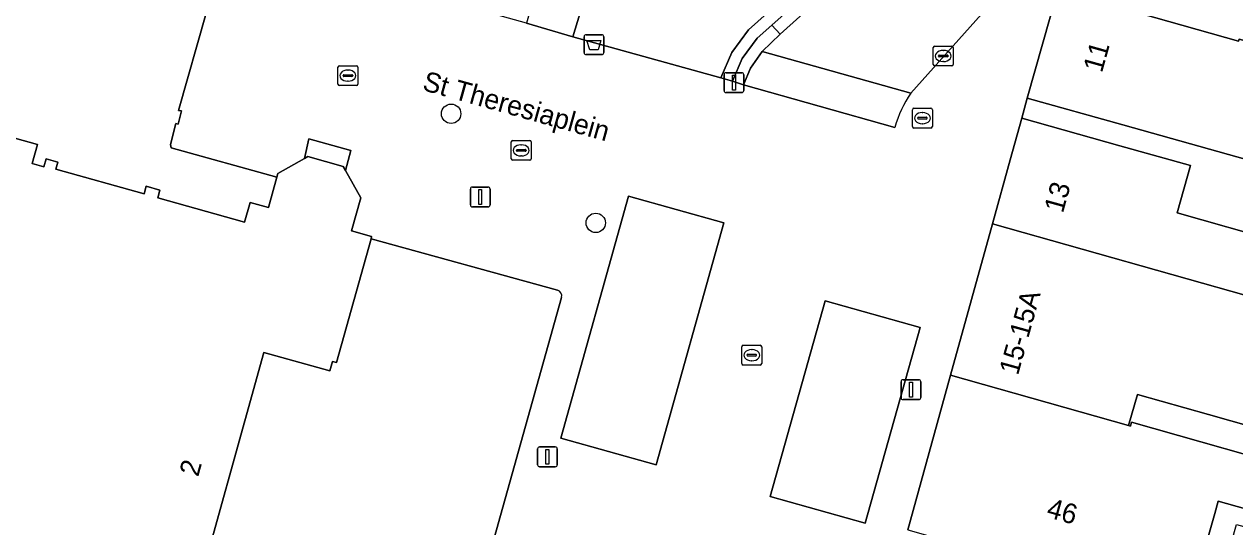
# Model space of a CAD drawing. Extents: x 158086 to 159499, y 382904 to 383981.
# Drawn here: x 158668.8 to 158729.8, y 383258 to 383283.3 of the extents above; entities that cross this region are included whole.
import ezdxf

# ---------------------------------------------------------------- set-up
doc = ezdxf.new("R2010")
doc.units = 0
for name, color, linetype in [('IMGEO_Afvalbak', 7, 'Continuous'), ('IMGEO_Boom', 7, 'Continuous'), ('IMGEO_Erf', 7, 'Continuous'), ('IMGEO_Groenvoorziening', 7, 'Continuous'), ('IMGEO_Haag', 7, 'Continuous'), ('IMGEO_Kolk', 7, 'Continuous'), ('IMGEO_Lichtmast', 7, 'Continuous'), ('IMGEO_Openbare_ruimte_label', 7, 'Continuous'), ('IMGEO_Pand', 7, 'Continuous'), ('IMGEO_Pand_nummerreeks', 7, 'Continuous'), ('IMGEO_Parkeervlak_open', 7, 'Continuous'), ('IMGEO_Rijbaan_lokaal_open', 7, 'Continuous'), ('IMGEO_Rioolput', 7, 'Continuous'), ('IMGEO_Voetpad_open', 7, 'Continuous')]:
    doc.layers.add(name, color=color, linetype=linetype)

msp = doc.modelspace()

# ---------------------------------------------------------------- linework, layer by layer
at = {"layer": 'IMGEO_Afvalbak'}
for p, q in [((158697.033, 383281.862), (158697.033, 383282.662)), ((158697.033, 383282.662), (158697.033, 383281.862)), ((158697.133, 383282.762), (158697.923, 383282.762)), ((158697.923, 383282.762), (158697.133, 383282.762)), ((158698.023, 383282.662), (158698.023, 383281.862)), ((158698.023, 383281.862), (158698.023, 383282.662)), ((158697.923, 383281.762), (158697.133, 383281.762)), ((158697.133, 383281.762), (158697.923, 383281.762))]:
    msp.add_line(p, q, dxfattribs=at)
msp.add_lwpolyline([(158697.176, 383282.476), (158697.88, 383282.476), (158697.731, 383282.006), (158697.325, 383282.006), (158697.176, 383282.476)], dxfattribs=at)
for centre, start, end in [((158697.133, 383282.662), 90, 180), ((158697.133, 383282.662), 90, 180), ((158697.923, 383282.662), 0, 90), ((158697.923, 383282.662), 360, 90), ((158697.133, 383281.862), 180, 270), ((158697.133, 383281.862), 180, 270), ((158697.923, 383281.862), 270, 0), ((158697.923, 383281.862), 270, 0)]:
    msp.add_arc(centre, 0.1, start, end, dxfattribs=at)
at = {"layer": 'IMGEO_Boom'}
for centre in [(158690.335, 383278.783), (158697.618, 383273.285)]:
    msp.add_circle(centre, 0.489, dxfattribs=at)
at = {"layer": 'IMGEO_Erf'}
for points in [[(158666.186, 383278.161), (158669.502, 383277.236), (158669.235, 383276.276), (158669.827, 383276.111), (158669.94, 383276.516), (158670.533, 383276.35), (158670.432, 383275.986), (158674.874, 383274.747), (158674.981, 383275.131), (158675.671, 383274.939), (158675.56, 383274.542), (158679.931, 383273.322), (158680.208, 383274.315), (158681.134, 383274.057), (158681.562, 383275.592), (158676.233, 383277.07), (158676.208, 383277.235), (158676.469, 383278.293), (158676.582, 383278.26), (158676.752, 383278.933), (158676.609, 383278.949), (158678, 383283.841), (158673.649, 383285.053), (158667.187, 383286.853)], [(158733.304, 383275.655), (158724.166, 383278.217), (158719.351, 383279.567), (158719.072, 383278.559), (158724.007, 383277.16), (158727.562, 383276.172), (158726.893, 383273.794), (158731.984, 383272.351)], [(158695.684, 383269.895), (158686.301, 383272.487), (158684.562, 383266.252), (158684.363, 383266.307), (158684.231, 383265.832), (158680.902, 383266.761), (158677.157, 383253.287)], [(158683.323, 383224.573), (158695.899, 383269.524)]]:
    msp.add_lwpolyline(points, dxfattribs=at)
msp.add_lwpolyline([(158731.056, 383257.778), (158731.292, 383258.611), (158728.963, 383259.271), (158728.786, 383258.646), (158727.422, 383253.835), (158731.469, 383252.723), (158731.473, 383252.737), (158731.567, 383253.068), (158731.35, 383253.13), (158730.129, 383253.476), (158728.69, 383253.884), (158729.885, 383258.097)], close=True, dxfattribs=at)
msp.add_arc((158695.601, 383269.599), 0.307, 345.85771, 74.32814, dxfattribs=at)
at = {"layer": 'IMGEO_Groenvoorziening'}
for points in [[(158715.651, 383319.137), (158708.346, 383292.883), (158713.145, 383291.584), (158712.877, 383290.631), (158712.4, 383289.615), (158711.72, 383288.771), (158708.905, 383286.24), (158705.305, 383283.005), (158704.465, 383281.869), (158703.916, 383280.587), (158704.499, 383280.425), (158704.989, 383281.568), (158705.749, 383282.597), (158706.491, 383283.248), (158709.467, 383285.933)], [(158701.326, 383284.735), (158697.345, 383285.602), (158696.463, 383282.664), (158703.916, 383280.587), (158704.465, 383281.869), (158705.305, 383283.005), (158708.905, 383286.24), (158708.372, 383286.529), (158707.006, 383286.118)]]:
    msp.add_lwpolyline(points, dxfattribs=at)
at = {"layer": 'IMGEO_Haag'}
msp.add_lwpolyline([(158715.651, 383319.137), (158708.346, 383292.883), (158713.145, 383291.584), (158712.877, 383290.631), (158712.4, 383289.615), (158711.72, 383288.771), (158708.905, 383286.24), (158705.305, 383283.005), (158704.465, 383281.869), (158703.916, 383280.587), (158704.499, 383280.425), (158704.989, 383281.568), (158705.749, 383282.597), (158706.491, 383283.248), (158709.467, 383285.933)], dxfattribs=at)
at = {"layer": 'IMGEO_Kolk'}
for p, q in [((158714.617, 383281.266), (158714.617, 383282.118)), ((158714.692, 383282.192), (158715.544, 383282.192)), ((158714.876, 383281.686), (158714.876, 383281.698)), ((158714.919, 383281.735), (158715.317, 383281.735)), ((158715.105, 383281.972), (158715.13, 383281.972)), ((158715.36, 383281.698), (158715.36, 383281.686)), ((158715.618, 383282.118), (158715.618, 383281.266)), ((158684.636, 383280.277), (158684.636, 383281.129)), ((158684.711, 383281.203), (158685.563, 383281.203)), ((158685.637, 383281.129), (158685.637, 383280.277)), ((158715.544, 383281.192), (158714.692, 383281.192)), ((158715.314, 383281.649), (158714.916, 383281.649)), ((158715.128, 383281.412), (158715.103, 383281.412)), ((158684.895, 383280.697), (158684.895, 383280.709)), ((158685.333, 383280.66), (158684.935, 383280.66)), ((158684.938, 383280.746), (158685.336, 383280.746)), ((158685.124, 383280.983), (158685.149, 383280.983)), ((158685.379, 383280.709), (158685.379, 383280.697)), ((158685.563, 383280.203), (158684.711, 383280.203)), ((158685.147, 383280.423), (158685.122, 383280.423)), ((158693.439, 383277.436), (158694.291, 383277.436)), ((158693.364, 383276.51), (158693.364, 383277.362)), ((158693.623, 383276.93), (158693.623, 383276.942)), ((158694.061, 383276.893), (158693.663, 383276.893)), ((158693.666, 383276.979), (158694.064, 383276.979)), ((158693.852, 383277.216), (158693.877, 383277.216)), ((158694.107, 383276.942), (158694.107, 383276.93)), ((158694.365, 383277.362), (158694.365, 383276.51)), ((158694.291, 383276.436), (158693.439, 383276.436)), ((158693.875, 383276.656), (158693.85, 383276.656)), ((158704.974, 383266.195), (158704.974, 383267.047)), ((158705.049, 383267.121), (158705.901, 383267.121)), ((158705.975, 383267.047), (158705.975, 383266.195)), ((158705.233, 383266.615), (158705.233, 383266.627)), ((158705.671, 383266.578), (158705.273, 383266.578)), ((158705.276, 383266.664), (158705.674, 383266.664)), ((158705.462, 383266.901), (158705.487, 383266.901)), ((158705.717, 383266.627), (158705.717, 383266.615)), ((158705.901, 383266.121), (158705.049, 383266.121)), ((158705.485, 383266.341), (158705.46, 383266.341))]:
    msp.add_line(p, q, dxfattribs=at)
for points in [[(158714.617, 383281.266), (158714.617, 383282.118)], [(158714.692, 383282.192), (158715.544, 383282.192)], [(158715.618, 383282.118), (158715.618, 383281.266)], [(158684.636, 383280.277), (158684.636, 383281.129)], [(158684.711, 383281.203), (158685.563, 383281.203)], [(158685.637, 383281.129), (158685.637, 383280.277)], [(158715.544, 383281.192), (158714.692, 383281.192)], [(158685.563, 383280.203), (158684.711, 383280.203)], [(158693.439, 383277.436), (158694.291, 383277.436)], [(158693.364, 383276.51), (158693.364, 383277.362)], [(158694.365, 383277.362), (158694.365, 383276.51)], [(158694.291, 383276.436), (158693.439, 383276.436)], [(158704.974, 383266.195), (158704.974, 383267.047)], [(158705.049, 383267.121), (158705.901, 383267.121)], [(158705.975, 383267.047), (158705.975, 383266.195)], [(158705.901, 383266.121), (158705.049, 383266.121)]]:
    msp.add_lwpolyline(points, dxfattribs=at)
for centre, radius, start, end in [((158714.694, 383282.116), 0.0765, 91.55205, 178.44795), ((158714.694, 383282.116), 0.0765, 91.55205, 178.44795), ((158714.916, 383281.695), 0.0403, 85.87752, 175.75265), ((158714.913, 383281.685), 0.0366, 178.93798, 274.71019), ((158715.317, 383281.692), 0.043, 264.86636, 352.45326), ((158715.321, 383281.697), 0.0386, 1.73085, 96.63898), ((158715.542, 383282.116), 0.0765, 1.55205, 88.44795), ((158715.542, 383282.116), 0.0765, 1.55205, 88.44795), ((158684.713, 383281.127), 0.0765, 91.55205, 178.44795), ((158684.713, 383281.127), 0.0765, 91.55205, 178.44795), ((158685.561, 383281.127), 0.0765, 1.55205, 88.44795), ((158685.561, 383281.127), 0.0765, 1.55205, 88.44795), ((158714.694, 383281.268), 0.0765, 181.55205, 268.44795), ((158714.694, 383281.268), 0.0765, 181.55205, 268.44795), ((158715.542, 383281.268), 0.0765, 271.55205, 358.44795), ((158715.542, 383281.268), 0.0765, 271.55205, 358.44795), ((158684.935, 383280.706), 0.0403, 85.87752, 175.75265), ((158684.932, 383280.696), 0.0366, 178.93798, 274.71019), ((158685.336, 383280.703), 0.043, 264.86636, 352.45326), ((158685.34, 383280.708), 0.0386, 1.73085, 96.63898), ((158684.713, 383280.279), 0.0765, 181.55205, 268.44795), ((158684.713, 383280.279), 0.0765, 181.55205, 268.44795), ((158685.561, 383280.279), 0.0765, 271.55205, 358.44795), ((158685.561, 383280.279), 0.0765, 271.55205, 358.44795), ((158693.441, 383277.36), 0.0765, 91.55205, 178.44795), ((158693.441, 383277.36), 0.0765, 91.55205, 178.44795), ((158694.289, 383277.36), 0.0765, 1.55205, 88.44795), ((158694.289, 383277.36), 0.0765, 1.55205, 88.44795), ((158693.663, 383276.939), 0.0403, 85.87752, 175.75265), ((158693.66, 383276.929), 0.0366, 178.93798, 274.71019), ((158694.064, 383276.936), 0.043, 264.86636, 352.45326), ((158694.068, 383276.941), 0.0386, 1.73085, 96.63898), ((158693.441, 383276.512), 0.0765, 181.55205, 268.44795), ((158693.441, 383276.512), 0.0765, 181.55205, 268.44795), ((158694.289, 383276.512), 0.0765, 271.55205, 358.44795), ((158694.289, 383276.512), 0.0765, 271.55205, 358.44795), ((158705.051, 383267.045), 0.0765, 91.55205, 178.44795), ((158705.051, 383267.045), 0.0765, 91.55205, 178.44795), ((158705.899, 383267.045), 0.0765, 1.55205, 88.44795), ((158705.899, 383267.045), 0.0765, 1.55205, 88.44795), ((158705.273, 383266.624), 0.0403, 85.87752, 175.75265), ((158705.27, 383266.614), 0.0366, 178.93798, 274.71019), ((158705.674, 383266.621), 0.043, 264.86636, 352.45326), ((158705.678, 383266.626), 0.0386, 1.73085, 96.63898), ((158705.051, 383266.197), 0.0765, 181.55205, 268.44795), ((158705.051, 383266.197), 0.0765, 181.55205, 268.44795), ((158705.899, 383266.197), 0.0765, 271.55205, 358.44795), ((158705.899, 383266.197), 0.0765, 271.55205, 358.44795)]:
    msp.add_arc(centre, radius, start, end, dxfattribs=at)
for centre, major_axis, ratio, start_param, end_param in [((158715.104, 383281.692), (-0.387, 0.002), 0.722429, 4.712389, 7.853982), ((158715.129, 383281.692), (-0.39, 0.002), 0.717154, 1.570796, 4.712389), ((158685.123, 383280.703), (-0.387, 0.002), 0.722429, 4.712389, 7.853982), ((158685.148, 383280.703), (-0.39, 0.002), 0.717154, 1.570796, 4.712389), ((158693.851, 383276.936), (-0.387, 0.002), 0.722429, 4.712389, 7.853982), ((158693.876, 383276.936), (-0.39, 0.002), 0.717154, 1.570796, 4.712389), ((158705.461, 383266.621), (-0.387, 0.002), 0.722429, 4.712389, 7.853982), ((158705.486, 383266.621), (-0.39, 0.002), 0.717154, 1.570796, 4.712389)]:
    msp.add_ellipse(centre, major_axis=major_axis, ratio=ratio, start_param=start_param, end_param=end_param, dxfattribs=at)
at = {"layer": 'IMGEO_Lichtmast'}
for p, q in [((158704.079, 383279.949), (158704.079, 383280.749)), ((158704.079, 383280.749), (158704.079, 383279.949)), ((158704.179, 383280.849), (158704.969, 383280.849)), ((158704.969, 383280.849), (158704.179, 383280.849)), ((158705.069, 383280.749), (158705.069, 383279.949)), ((158705.069, 383279.949), (158705.069, 383280.749)), ((158704.969, 383279.849), (158704.179, 383279.849)), ((158704.179, 383279.849), (158704.969, 383279.849)), ((158691.302, 383274.19), (158691.302, 383274.99)), ((158691.302, 383274.99), (158691.302, 383274.19)), ((158691.402, 383275.09), (158692.192, 383275.09)), ((158692.192, 383275.09), (158691.402, 383275.09)), ((158692.292, 383274.99), (158692.292, 383274.19)), ((158692.292, 383274.19), (158692.292, 383274.99)), ((158692.192, 383274.09), (158691.402, 383274.09)), ((158691.402, 383274.09), (158692.192, 383274.09)), ((158712.992, 383264.483), (158712.992, 383265.283)), ((158712.992, 383265.283), (158712.992, 383264.483)), ((158713.092, 383265.383), (158713.882, 383265.383)), ((158713.882, 383265.383), (158713.092, 383265.383)), ((158713.982, 383265.283), (158713.982, 383264.483)), ((158713.982, 383264.483), (158713.982, 383265.283)), ((158713.882, 383264.383), (158713.092, 383264.383)), ((158713.092, 383264.383), (158713.882, 383264.383)), ((158694.689, 383261.098), (158694.689, 383261.898)), ((158694.689, 383261.898), (158694.689, 383261.098)), ((158694.789, 383261.998), (158695.579, 383261.998)), ((158695.579, 383261.998), (158694.789, 383261.998)), ((158695.679, 383261.898), (158695.679, 383261.098)), ((158695.679, 383261.098), (158695.679, 383261.898)), ((158695.579, 383260.998), (158694.789, 383260.998)), ((158694.789, 383260.998), (158695.579, 383260.998))]:
    msp.add_line(p, q, dxfattribs=at)
for points in [[(158704.499, 383280.724), (158704.649, 383280.724), (158704.649, 383279.974), (158704.499, 383279.974), (158704.499, 383280.724)], [(158691.722, 383274.965), (158691.872, 383274.965), (158691.872, 383274.215), (158691.722, 383274.215), (158691.722, 383274.965)], [(158713.412, 383265.258), (158713.562, 383265.258), (158713.562, 383264.508), (158713.412, 383264.508), (158713.412, 383265.258)], [(158695.109, 383261.873), (158695.259, 383261.873), (158695.259, 383261.123), (158695.109, 383261.123), (158695.109, 383261.873)]]:
    msp.add_lwpolyline(points, dxfattribs=at)
for centre, start, end in [((158704.179, 383280.749), 90, 180), ((158704.179, 383280.749), 90, 180), ((158704.969, 383280.749), 0, 90), ((158704.969, 383280.749), 360, 90), ((158704.179, 383279.949), 180, 270), ((158704.179, 383279.949), 180, 270), ((158704.969, 383279.949), 270, 0), ((158704.969, 383279.949), 270, 0), ((158691.402, 383274.99), 90, 180), ((158691.402, 383274.99), 90, 180), ((158692.192, 383274.99), 0, 90), ((158692.192, 383274.99), 360, 90), ((158691.402, 383274.19), 180, 270), ((158691.402, 383274.19), 180, 270), ((158692.192, 383274.19), 270, 0), ((158692.192, 383274.19), 270, 0), ((158713.092, 383265.283), 90, 180), ((158713.092, 383265.283), 90, 180), ((158713.882, 383265.283), 0, 90), ((158713.882, 383265.283), 360, 90), ((158713.092, 383264.483), 180, 270), ((158713.092, 383264.483), 180, 270), ((158713.882, 383264.483), 270, 0), ((158713.882, 383264.483), 270, 0), ((158694.789, 383261.898), 90, 180), ((158694.789, 383261.898), 90, 180), ((158695.579, 383261.898), 0, 90), ((158695.579, 383261.898), 360, 90), ((158694.789, 383261.098), 180, 270), ((158694.789, 383261.098), 180, 270), ((158695.579, 383261.098), 270, 0), ((158695.579, 383261.098), 270, 0)]:
    msp.add_arc(centre, 0.1, start, end, dxfattribs=at)
at = {"layer": 'IMGEO_Pand'}
for points in [[(158747.117, 383286.346), (158737.135, 383289.145), (158727.954, 383291.719), (158723.139, 383293.069), (158720.882, 383285.022), (158729.99, 383282.438), (158730.021, 383282.546), (158734.867, 383281.172), (158742.063, 383279.133), (158745.03, 383278.292), (158745.391, 383279.615), (158745.223, 383279.663)], [(158734.867, 383281.172), (158730.021, 383282.546), (158729.99, 383282.438), (158720.882, 383285.022), (158719.351, 383279.567), (158724.166, 383278.217), (158733.304, 383275.655), (158734.145, 383278.623)], [(158717.6, 383273.245), (158731.149, 383269.404), (158731.984, 383272.351), (158726.893, 383273.794), (158727.562, 383276.172), (158724.007, 383277.16), (158719.072, 383278.559), (158718.49, 383276.457)], [(158741.746, 383266.399), (158735.14, 383268.272), (158731.149, 383269.404), (158717.6, 383273.245), (158715.488, 383265.62), (158724.45, 383263.079), (158724.892, 383264.641), (158728.468, 383263.628), (158734.337, 383261.965), (158735.745, 383261.566), (158736.861, 383262.215), (158737.084, 383263.003), (158738.717, 383262.54), (158738.599, 383262.125), (158737.851, 383259.485), (158739.657, 383258.977), (158739.895, 383259.821)], [(158733.948, 383260.591), (158724.597, 383263.242), (158724.543, 383263.053), (158724.45, 383263.079), (158715.488, 383265.62), (158713.33, 383257.83), (158727.422, 383253.835), (158728.786, 383258.646), (158728.963, 383259.271), (158731.292, 383258.611), (158731.056, 383257.778), (158732.08, 383257.499), (158732.767, 383257.312), (158732.836, 383257.558), (158733.859, 383257.268), (158734.241, 383257.16), (158735.066, 383260.069), (158735.12, 383260.259)], [(158728.468, 383263.628), (158724.892, 383264.641), (158724.45, 383263.079), (158724.543, 383263.053), (158724.597, 383263.242), (158733.948, 383260.591), (158734.337, 383261.965)]]:
    msp.add_lwpolyline(points, close=True, dxfattribs=at)
msp.add_lwpolyline([(158677.157, 383253.287), (158680.902, 383266.761), (158684.231, 383265.832), (158684.363, 383266.307), (158684.562, 383266.252), (158686.301, 383272.487), (158686.332, 383272.598), (158685.317, 383272.881), (158685.784, 383274.551), (158685.007, 383275.93), (158684.896, 383276.126), (158683.116, 383276.623), (158682.943, 383276.526), (158681.613, 383275.776), (158681.562, 383275.592), (158681.134, 383274.057), (158680.208, 383274.315), (158679.931, 383273.322), (158675.56, 383274.542), (158675.671, 383274.939), (158674.981, 383275.131), (158674.874, 383274.747), (158670.432, 383275.986), (158670.533, 383276.35), (158669.94, 383276.516), (158669.827, 383276.111), (158669.235, 383276.276), (158669.502, 383277.236), (158666.186, 383278.161)], dxfattribs=at)
at = {"layer": 'IMGEO_Parkeervlak_open'}
for points in [[(158700.662, 383261.103), (158704.071, 383273.29), (158699.27, 383274.633), (158695.861, 383262.446)], [(158711.189, 383258.167), (158713.954, 383268.023), (158709.174, 383269.365), (158706.409, 383259.508)]]:
    msp.add_lwpolyline(points, close=True, dxfattribs=at)
at = {"layer": 'IMGEO_Rijbaan_lokaal_open'}
for points in [[(158712.839, 383288.156), (158712.19, 383287.558), (158706.901, 383282.787), (158706, 383281.923), (158713.492, 383279.816), (158718.325, 383285.237)], [(158706, 383281.923), (158705.414, 383281.076), (158705.06, 383280.231)], [(158713.492, 383279.816), (158706, 383281.923)], [(158705.06, 383280.231), (158712.681, 383278.089)]]:
    msp.add_lwpolyline(points, dxfattribs=at)
msp.add_arc((158717.932, 383276.677), 5.438, 144.74116, 164.94929, dxfattribs=at)
at = {"layer": 'IMGEO_Rioolput'}
for p, q in [((158713.568, 383278.134), (158713.568, 383278.986)), ((158713.643, 383279.06), (158714.495, 383279.06)), ((158714.056, 383278.84), (158714.081, 383278.84)), ((158714.569, 383278.986), (158714.569, 383278.134)), ((158714.495, 383278.06), (158713.643, 383278.06)), ((158713.827, 383278.554), (158713.827, 383278.566)), ((158714.265, 383278.517), (158713.867, 383278.517)), ((158713.87, 383278.603), (158714.268, 383278.603)), ((158714.079, 383278.28), (158714.054, 383278.28)), ((158714.311, 383278.566), (158714.311, 383278.554))]:
    msp.add_line(p, q, dxfattribs=at)
for points in [[(158713.568, 383278.134), (158713.568, 383278.986)], [(158713.643, 383279.06), (158714.495, 383279.06)], [(158714.569, 383278.986), (158714.569, 383278.134)], [(158714.495, 383278.06), (158713.643, 383278.06)]]:
    msp.add_lwpolyline(points, dxfattribs=at)
for centre, radius, start, end in [((158713.645, 383278.984), 0.0765, 91.55205, 178.44795), ((158713.645, 383278.984), 0.0765, 91.55205, 178.44795), ((158714.493, 383278.984), 0.0765, 1.55205, 88.44795), ((158714.493, 383278.984), 0.0765, 1.55205, 88.44795), ((158713.645, 383278.136), 0.0765, 181.55205, 268.44795), ((158713.645, 383278.136), 0.0765, 181.55205, 268.44795), ((158713.867, 383278.563), 0.0403, 85.87752, 175.75265), ((158713.864, 383278.553), 0.0366, 178.93798, 274.71019), ((158714.268, 383278.56), 0.043, 264.86636, 352.45326), ((158714.272, 383278.565), 0.0386, 1.73085, 96.63898), ((158714.493, 383278.136), 0.0765, 271.55205, 358.44795), ((158714.493, 383278.136), 0.0765, 271.55205, 358.44795)]:
    msp.add_arc(centre, radius, start, end, dxfattribs=at)
for centre, major_axis, ratio, start_param, end_param in [((158714.055, 383278.56), (-0.387, 0.002), 0.722429, 4.712389, 7.853982), ((158714.08, 383278.56), (-0.39, 0.002), 0.717154, 1.570796, 4.712389)]:
    msp.add_ellipse(centre, major_axis=major_axis, ratio=ratio, start_param=start_param, end_param=end_param, dxfattribs=at)
at = {"layer": 'IMGEO_Voetpad_open'}
for points in [[(158712.681, 383278.089), (158705.06, 383280.231), (158704.499, 383280.425), (158703.916, 383280.587), (158696.463, 383282.664), (158694.138, 383283.337), (158683.206, 383286.407), (158683.014, 383286.461), (158682.436, 383286.623), (158684.564, 383294.149), (158692.698, 383323.292)], [(158693.404, 383323.589), (158695.344, 383314.668), (158698.657, 383299.429), (158698.135, 383297.568), (158695.081, 383286.692), (158694.138, 383283.337), (158696.463, 383282.664), (158697.345, 383285.602), (158700.848, 383298.094), (158703.141, 383306.283)], [(158713.33, 383257.83), (158715.488, 383265.62), (158717.6, 383273.245), (158718.49, 383276.457), (158719.072, 383278.559), (158719.351, 383279.567), (158720.882, 383285.022), (158723.139, 383293.069), (158723.419, 383294.014), (158724.891, 383299.284), (158726.38, 383304.619), (158726.638, 383305.589), (158728.013, 383310.572), (158729.552, 383311.413), (158726.409, 383312.281), (158719.408, 383287.329)], [(158718.325, 383285.237), (158713.492, 383279.816)], [(158678, 383283.841), (158676.609, 383278.949), (158676.752, 383278.933), (158676.582, 383278.26), (158676.469, 383278.293), (158676.208, 383277.235), (158676.233, 383277.07), (158681.562, 383275.592), (158681.613, 383275.776), (158682.943, 383276.526), (158683.169, 383277.526), (158685.291, 383276.933), (158685.007, 383275.93), (158685.784, 383274.551), (158685.317, 383272.881), (158686.332, 383272.598), (158686.301, 383272.487), (158695.684, 383269.895)], [(158695.899, 383269.524), (158683.323, 383224.573)]]:
    msp.add_lwpolyline(points, dxfattribs=at)
for points in [[(158706.491, 383283.248), (158706.901, 383282.787), (158712.19, 383287.558), (158711.776, 383288.016), (158709.467, 383285.933)], [(158706.491, 383283.248), (158705.749, 383282.597), (158704.989, 383281.568), (158704.499, 383280.425), (158705.06, 383280.231), (158705.414, 383281.076), (158706, 383281.923), (158706.901, 383282.787)], [(158683.116, 383276.623), (158684.896, 383276.126), (158685.007, 383275.93), (158685.291, 383276.933), (158683.169, 383277.526), (158682.943, 383276.526)], [(158699.27, 383274.633), (158704.071, 383273.29), (158700.662, 383261.103), (158695.861, 383262.446)], [(158709.174, 383269.365), (158713.954, 383268.023), (158711.189, 383258.167), (158706.409, 383259.508)]]:
    msp.add_lwpolyline(points, close=True, dxfattribs=at)
for centre, radius, start, end in [((158717.932, 383276.677), 5.438, 144.74116, 164.94929), ((158695.601, 383269.599), 0.307, 345.85771, 74.32814)]:
    msp.add_arc(centre, radius, start, end, dxfattribs=at)

# ---------------------------------------------------------------- texts
at = {"layer": 'IMGEO_Openbare_ruimte_label'}
msp.add_text('St Theresiaplein', height=1, rotation=344.39307, dxfattribs=at).set_placement((158688.835, 383279.986))
at = {"layer": 'IMGEO_Pand_nummerreeks'}
for s, rotation, p in [('11', 74.32409, (158723.107, 383280.81)), ('13', 74.51769, (158721.141, 383273.739)), ('15-15A', 74.51889, (158718.879, 383265.573)), ('2', 74.46732, (158677.593, 383260.46)), ('46', 344.17491, (158720.268, 383258.482))]:
    msp.add_text(s, height=1, rotation=rotation, dxfattribs=at).set_placement(p)

doc.saveas('drawing.dxf')
